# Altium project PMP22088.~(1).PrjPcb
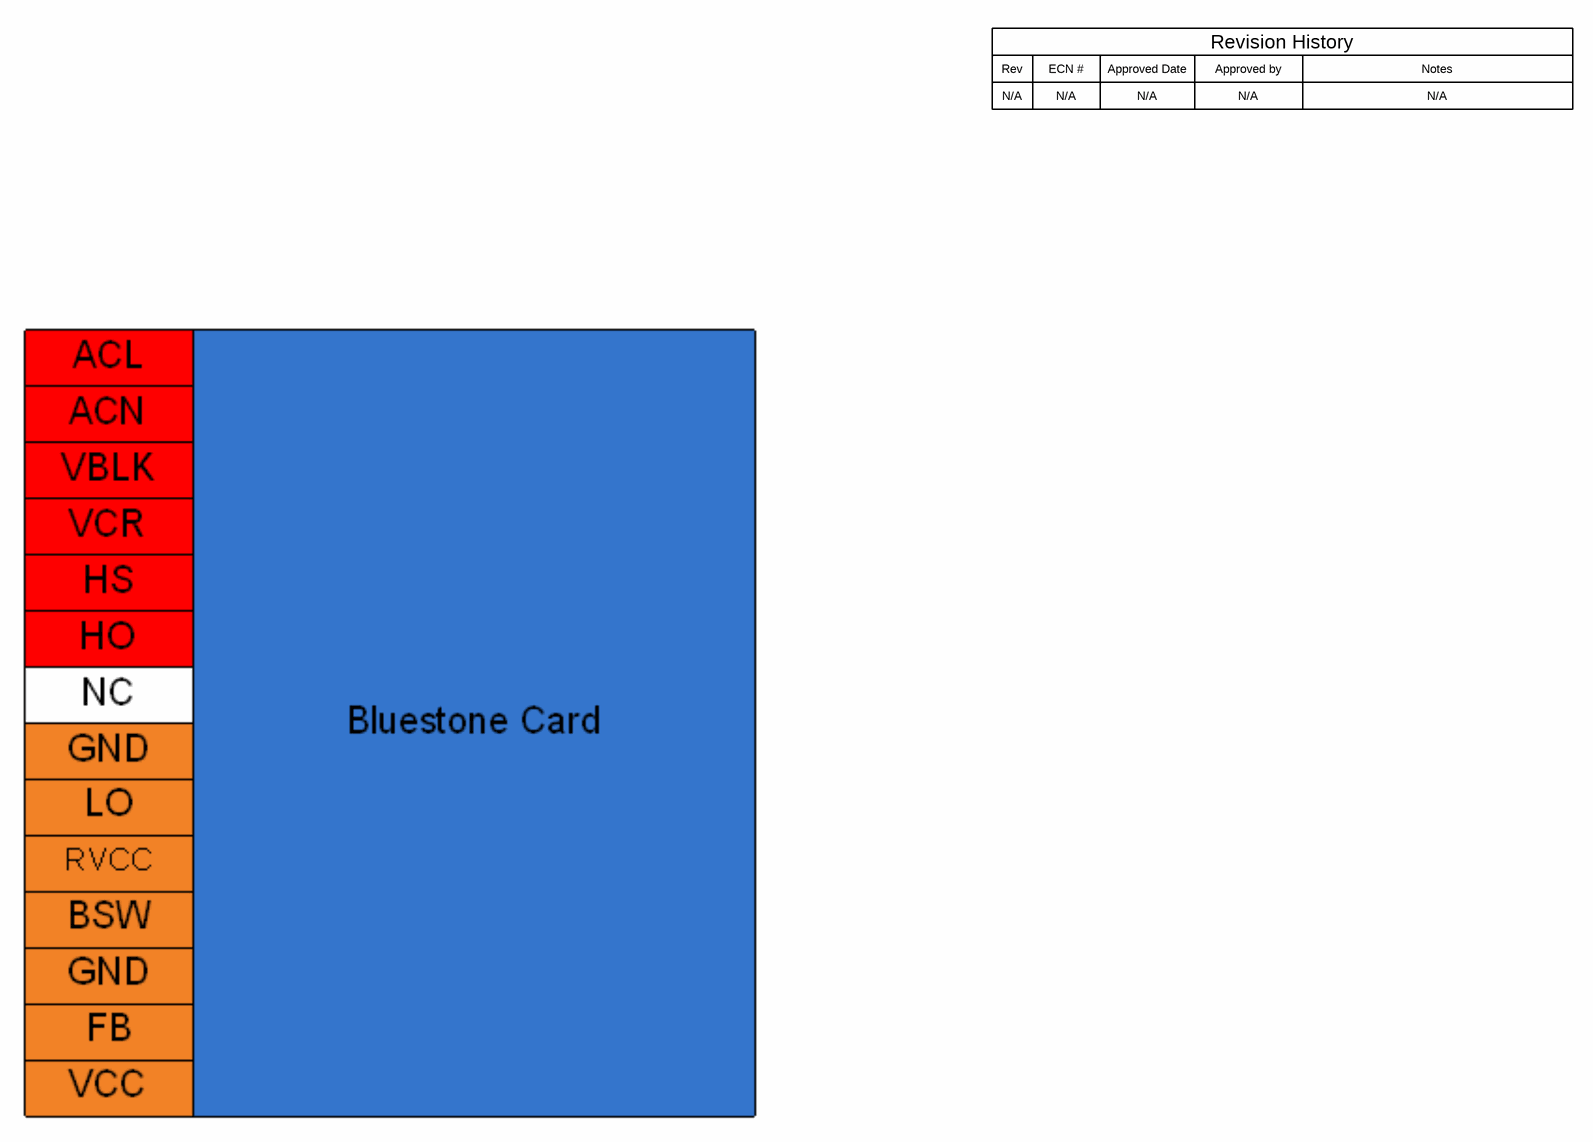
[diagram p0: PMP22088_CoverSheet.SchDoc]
CopyrightYear: 2018; PCB_Layout: Who did the Layout?; PCB_Rev: E1; PRJ_Customer: Public Release; PRJ_Engineer: Enter name of project lead; PRJ_Number: XX####; PRJ_Title: Change in menu Project|Project Options|Parameters; SCH_Rev: E1; TechSupport: http://www.ti.com/support; TID: N/A
1 sheet, 0 parts. Net scope: global (net labels, ports and power ports of the same name join across sheets).
Board file: PMP22088_PCB.PcbDoc

## Sheet PMP22088_CoverSheet.SchDoc
size 431 x 279 mm; Date: Not shown in title block; ApprovedBy: Not shown in title block; CheckedBy: Not shown in title block; Author: Not shown in title block; CompanyName: Not shown in title block; Engineer: Not shown in title block; Organization: Not shown in title block; Address1: Not shown in title block; Address2: Not shown in title block; Address3: Not shown in title block; Address4: Not shown in title block; DocumentNumber: 1; Revision: Use project parameter SCH_Rev; SheetNumber: 1; SheetTotal: 3; PageSetup: Record=PageOptions¦CenterHorizontal=True¦CenterVertical=True¦PrintScale=1.00¦XCorrection=1.00¦YCorrection=1.00¦PrintKind=0¦BorderSize=5000000¦LeftOffset=0¦BottomOffset=0¦Orientation=2¦PaperLength=1000¦PaperWidth=1000¦Scale=100¦PaperSource=15¦PrintQuality=600¦MediaType=1¦DitherType=10¦PaperKind=Letter¦PrintScaleMode=1

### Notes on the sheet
- Rev
- N/A
- ECN #
- Approved Date
- Approved by
- Revision History
- Notes

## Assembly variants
001: not fitted FID1 FID2 FID3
